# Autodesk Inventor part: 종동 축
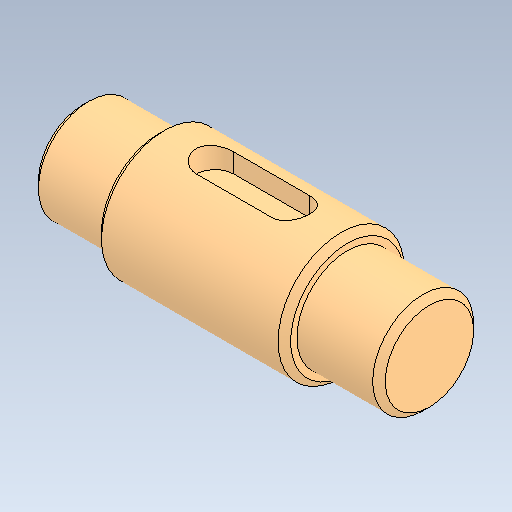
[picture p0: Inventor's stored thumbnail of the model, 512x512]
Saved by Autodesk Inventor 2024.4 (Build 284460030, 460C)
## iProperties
Created: 2026-09
Part Number: 종동 축
Material: 강철, 탄소
Document SubType Name: Modeling
Designer: user
Density: 7.85 g/cm^3
Appearance: 기본값
Sending System: Autodesk Inventor 2027
Preprocessor: ST-DEVELOPER v20.1
Author: jhkim
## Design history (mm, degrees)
feature "솔리드1"
node "솔리드2"
